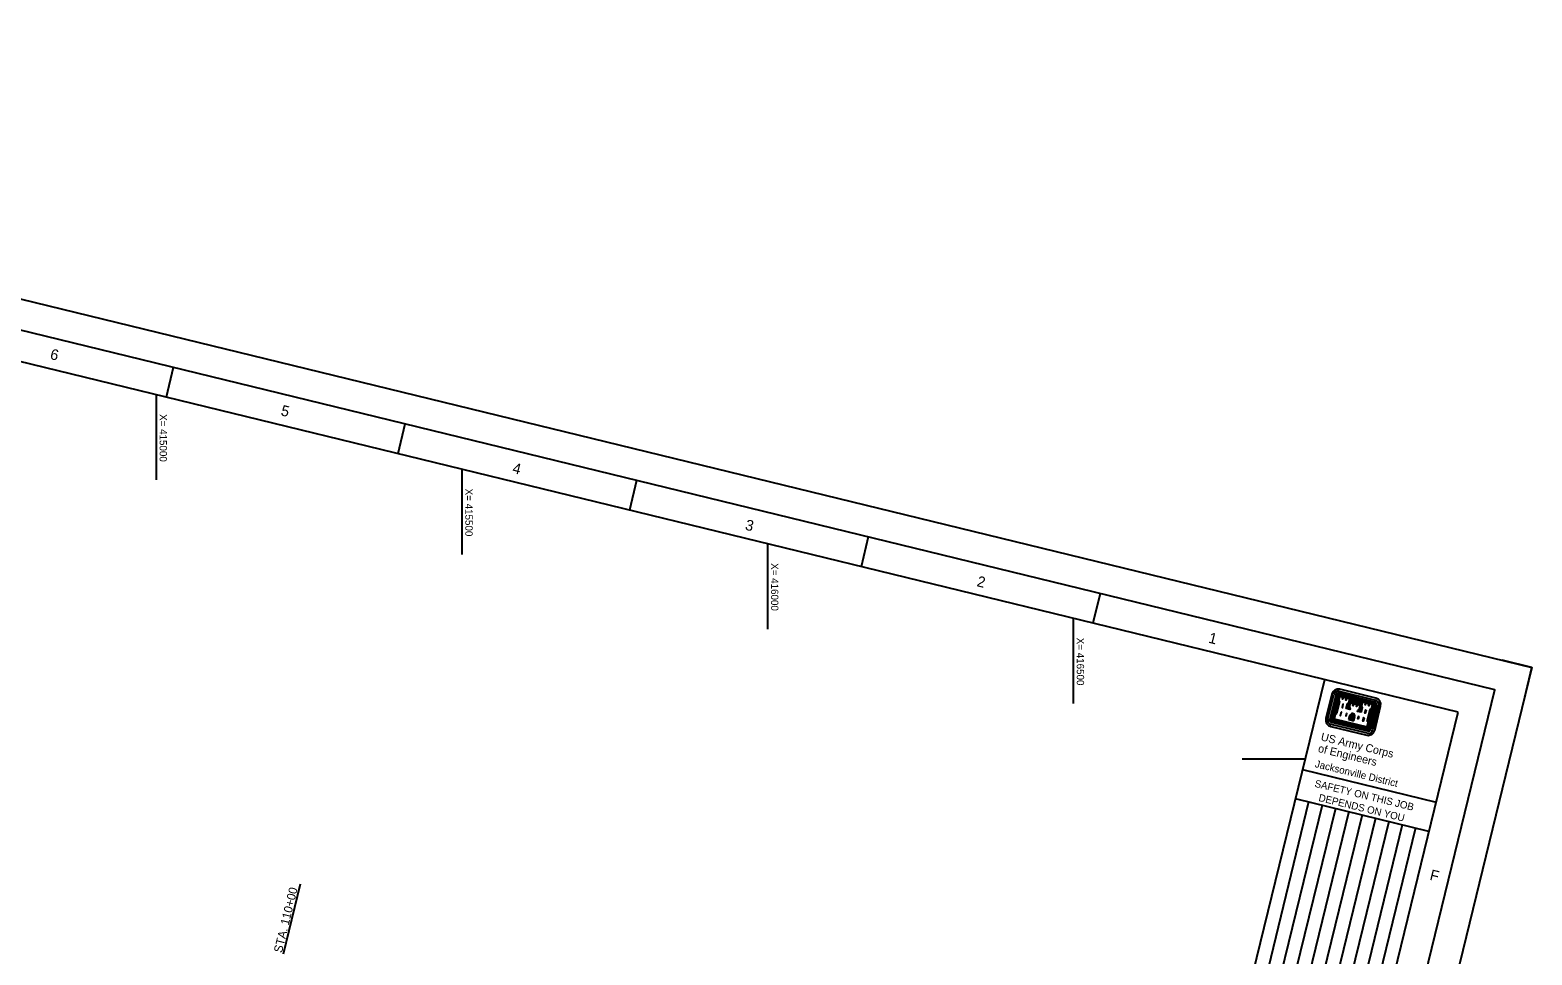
# Model space of a CAD drawing. Extents: x 412170 to 417250, y 1187847 to 1192192.
# Drawn here: x 414793 to 417250, y 1190679 to 1192192 of the extents above; entities that cross this region are included whole.
import ezdxf

# ---------------------------------------------------------------- set-up
doc = ezdxf.new("R2010")
doc.units = 0
for name, color, linetype in [('G-ANNO-NPLT', 7, 'Continuous'), ('G-ANNO-TEXT-LOGO', 7, 'Continuous'), ('G-ANNO-TEXT-TTLB', 7, 'Continuous'), ('G-ANNO-TTLB', 7, 'Continuous'), ('V-ALGN-TEXT', 7, 'Continuous'), ('V-TOPO-COOR-STAT', 7, 'Continuous')]:
    doc.layers.add(name, color=color, linetype=linetype)

msp = doc.modelspace()

# ---------------------------------------------------------------- linework, layer by layer
at = {"layer": 'G-ANNO-NPLT'}
msp.add_lwpolyline([(412975.1, 1192192.3), (417249.8, 1191149.8), (416444.2, 1187846.7), (412169.5, 1188889.2)], close=True, dxfattribs=at)
msp.add_lwpolyline([(417237.9, 1191101.3), (417249.8, 1191149.8), (417201.2, 1191161.7)], dxfattribs=at)
at = {"layer": 'G-ANNO-TEXT-LOGO'}
for p, q in [((416922.4, 1191106.1), (416912.7, 1191066.2)), ((416915.8, 1191065.5), (416925.5, 1191105.3)), ((416928.9, 1191104.5), (416919.2, 1191064.6)), ((416929.8, 1191104.3), (416920.1, 1191064.4)), ((416930.6, 1191104.1), (416920.9, 1191064.2)), ((416931.5, 1191103.9), (416921.7, 1191064)), ((416932.3, 1191103.6), (416922.6, 1191063.8)), ((416933.2, 1191103.4), (416923.6, 1191063.9)), ((416934, 1191103.2), (416924.6, 1191064.6)), ((416932.6, 1191094.6), (416927.6, 1191074.2)), ((416933.3, 1191093.5), (416928.7, 1191075)), ((416992, 1191089.7), (416933, 1191104.1)), ((416992.2, 1191090.6), (416933.2, 1191105)), ((416992.4, 1191091.3), (416933.4, 1191105.8)), ((416992.7, 1191092.2), (416933.6, 1191106.6)), ((416992.9, 1191093.1), (416933.8, 1191107.5)), ((416934.6, 1191110.8), (416993.7, 1191096.4)), ((416994.4, 1191099.5), (416935.4, 1191113.9)), ((416952, 1191093.3), (416970.1, 1191088.9)), ((416952.3, 1191094.1), (416970.3, 1191089.7)), ((416952.4, 1191094.9), (416970.5, 1191090.5)), ((416952.7, 1191095.8), (416970.7, 1191091.4)), ((416952.9, 1191096.7), (416970.9, 1191092.3)), ((416953.1, 1191097.5), (416971.1, 1191093)), ((416953.3, 1191098.3), (416971.3, 1191093.9)), ((416950.4, 1191064.3), (416952, 1191070.8)), ((416951.2, 1191064.1), (416952.8, 1191070.6)), ((416952.1, 1191063.9), (416953.7, 1191070.4)), ((416953, 1191063.7), (416954.6, 1191070.2)), ((416953.7, 1191063.5), (416955.3, 1191070)), ((416954.9, 1191063.2), (416956.5, 1191069.7)), ((416955.7, 1191063.1), (416957.3, 1191069.6)), ((416956.6, 1191062.8), (416958.1, 1191069.3)), ((416957.4, 1191062.6), (416959, 1191069.1)), ((416958.2, 1191062.4), (416959.8, 1191068.9)), ((416990.7, 1191089.4), (416981.3, 1191050.7)), ((416991.5, 1191089.2), (416981.9, 1191049.7)), ((416986.9, 1191080.5), (416982.4, 1191061.9)), ((416992.4, 1191089), (416982.7, 1191049.2)), ((416988, 1191081), (416983, 1191060.8)), ((416993.3, 1191088.8), (416983.5, 1191049)), ((416994, 1191088.6), (416984.3, 1191048.8)), ((416994.9, 1191088.4), (416985.2, 1191048.5)), ((416995.8, 1191088.2), (416986.1, 1191048.3)), ((416999.1, 1191087.4), (416989.4, 1191047.5)), ((416992.6, 1191046.7), (417002.3, 1191086.6)), ((416920.6, 1191053.2), (416979.6, 1191038.8)), ((416980.4, 1191042), (416921.3, 1191056.4)), ((416981.2, 1191045.4), (416922.2, 1191059.8)), ((416981.4, 1191046.2), (416922.4, 1191060.6)), ((416981.6, 1191047), (416922.6, 1191061.5)), ((416981.8, 1191047.9), (416922.8, 1191062.3)), ((416982, 1191048.7), (416923, 1191063.1)), ((416981.9, 1191049.7), (416923.6, 1191063.9)), ((416981.3, 1191050.7), (416924.6, 1191064.6)), ((416950.4, 1191064.3), (416958.2, 1191062.4))]:
    msp.add_line(p, q, dxfattribs=at)
for points in [[(416934.7, 1191103.1), (416932.8, 1191095.4), (416934, 1191093.3), (416929.5, 1191074.8), (416927.4, 1191073.4), (416925.4, 1191065), (416980.8, 1191051.5), (416982.8, 1191059.9), (416981.5, 1191062.1), (416986, 1191080.7), (416988.2, 1191081.9), (416990, 1191089.6), (416982.8, 1191091.3), (416977.1, 1191092.7), (416971.9, 1191094), (416970, 1191086.3), (416971.5, 1191084.2), (416969.8, 1191077.4), (416965.7, 1191078.4), (416965.9, 1191079.1), (416968.1, 1191080.4), (416969.9, 1191088), (416962.6, 1191089.8), (416957, 1191091.1), (416951.8, 1191092.4), (416950, 1191084.8), (416951.3, 1191082.6), (416951.1, 1191082), (416947.1, 1191083), (416948.7, 1191089.8), (416950.9, 1191091), (416952.7, 1191098.7), (416945.5, 1191100.4), (416939.8, 1191101.8), (416934.7, 1191103.1)], [(416935.2, 1191102), (416933.7, 1191095.6), (416935, 1191093.4), (416930.3, 1191074.2), (416928.1, 1191072.9), (416926.4, 1191065.7), (416980.2, 1191052.5), (416981.9, 1191059.7), (416980.5, 1191061.9), (416985.2, 1191081.2), (416987.5, 1191082.5), (416989.1, 1191088.9), (416983.8, 1191090.2), (416983.1, 1191087.1), (416982.6, 1191087.3), (416983.3, 1191090.3), (416978.2, 1191091.5), (416977.4, 1191088.5), (416977.1, 1191088.6), (416977.8, 1191091.6), (416972.5, 1191092.9), (416971, 1191086.5), (416972.3, 1191084.3), (416970.4, 1191076.5), (416964.7, 1191077.8), (416965.2, 1191079.7), (416967.4, 1191081), (416968.9, 1191087.4), (416963.7, 1191088.7), (416963, 1191085.7), (416962.6, 1191085.8), (416963.3, 1191088.8), (416958.1, 1191090.1), (416957.3, 1191087), (416956.8, 1191087.2), (416957.6, 1191090.2), (416952.4, 1191091.4), (416950.9, 1191085), (416952.2, 1191082.8), (416951.7, 1191081), (416946.1, 1191082.4), (416948, 1191090.2), (416950.2, 1191091.6), (416951.7, 1191098), (416946.6, 1191099.2), (416945.9, 1191096.2), (416945.4, 1191096.3), (416946.1, 1191099.4), (416940.9, 1191100.6), (416940.1, 1191097.6), (416939.7, 1191097.7), (416940.5, 1191100.7), (416935.2, 1191102)], [(416937.5, 1191076.7), (416936.1, 1191071), (416936.7, 1191070.9), (416938.1, 1191076.6), (416937.5, 1191076.7)], [(416940.7, 1191089.7), (416939.3, 1191084), (416939.9, 1191083.9), (416941.2, 1191089.5), (416940.7, 1191089.7)], [(416946.5, 1191074.6), (416945.5, 1191070.6), (416946, 1191070.5), (416946.9, 1191074.4), (416946.5, 1191074.6)], [(416950.1, 1191089.5), (416949.5, 1191089.2), (416948.1, 1191083.6), (416950, 1191083.2), (416949, 1191084.7), (416950.2, 1191089.6)], [(416966.5, 1191069.7), (416965.5, 1191065.7), (416965, 1191065.8), (416966, 1191069.8), (416966.5, 1191069.7)], [(416970.1, 1191084.6), (416970.5, 1191084), (416969.1, 1191078.5), (416967.4, 1191078.9), (416968.9, 1191079.9), (416970, 1191084.8)], [(416975.3, 1191067.5), (416973.9, 1191061.8), (416973.4, 1191061.9), (416974.8, 1191067.6), (416975.3, 1191067.5)], [(416978.5, 1191080.5), (416977.1, 1191074.8), (416976.6, 1191074.9), (416978, 1191080.6), (416978.5, 1191080.5)]]:
    msp.add_lwpolyline(points, dxfattribs=at)
for centre, major_axis, start_param, end_param in [((416932.9, 1191103.5), (10.4, -2.5), 1.57078, 3.141576), ((416932.9, 1191103.5), (7.28, -1.77), 1.57078, 3.141576), ((416932.9, 1191103.5), (3.9, -0.95), 1.57078, 3.141576), ((416932.9, 1191103.5), (3.06, -0.75), 1.57078, 3.141576), ((416932.9, 1191103.5), (2.22, -0.54), 1.57078, 3.141576), ((416932.9, 1191103.5), (1.37, -0.33), 1.57078, 3.141576), ((416932.9, 1191103.5), (0.53, -0.129), 1.57078, 3.141576), ((416991.8, 1191089.1), (2.22, -0.54), 6.283169, 7.853965), ((416991.8, 1191089.1), (3.06, -0.75), 6.283169, 7.853965), ((416991.8, 1191089.1), (3.9, -0.95), 6.283169, 7.853965), ((416991.8, 1191089.1), (7.28, -1.77), 6.28317, 7.853966), ((416991.8, 1191089.1), (10.4, -2.5), 6.283169, 7.853965), ((416923.1, 1191063.6), (-10.4, 2.5), 6.28317, 7.853966), ((416957.2, 1191069.1), (-5.4, 1.32), 4.985832, 6.214359), ((416957.2, 1191069.1), (-4.55, 1.11), 4.947465, 6.21436), ((416957.2, 1191069.1), (-3.71, 0.9), 4.947465, 6.21436), ((416957.2, 1191069.1), (-2.87, 0.7), 4.947465, 6.21436), ((416954.3, 1191069.8), (2.02, -0.49), 0.068794, 1.335689), ((416957.2, 1191069.1), (-2.02, 0.49), 4.947465, 6.214359), ((416954.3, 1191069.8), (2.87, -0.7), 0.068794, 1.335689), ((416954.3, 1191069.8), (3.71, -0.9), 0.068795, 1.335689), ((416954.3, 1191069.8), (4.55, -1.11), 0.068795, 1.335689), ((416954.3, 1191069.8), (5.4, -1.32), 0.068795, 1.29842), ((416991.8, 1191089.1), (0.53, -0.129), 6.283169, 7.853965), ((416991.8, 1191089.1), (1.37, -0.33), 6.283169, 7.853965), ((416923.1, 1191063.6), (-7.28, 1.77), 6.28317, 7.853966), ((416923.1, 1191063.6), (-3.9, 0.95), 6.28317, 7.853966), ((416923.1, 1191063.6), (-3.06, 0.75), 6.28317, 7.853966), ((416923.1, 1191063.6), (-2.22, 0.54), 6.28317, 7.853966), ((416923.1, 1191063.6), (-1.37, 0.33), 6.28317, 7.853966), ((416923.1, 1191063.6), (-0.53, 0.129), 6.28317, 7.853966), ((416982.1, 1191049.3), (10.4, -2.5), 4.712373, 6.28317), ((416982.1, 1191049.3), (-7.28, 1.77), 1.570781, 3.141577), ((416982.1, 1191049.3), (3.9, -0.95), 4.712373, 6.28317), ((416982.1, 1191049.3), (3.06, -0.75), 4.712373, 6.28317), ((416982.1, 1191049.3), (2.22, -0.54), 4.712373, 6.28317), ((416982.1, 1191049.3), (1.37, -0.33), 4.712373, 6.28317), ((416982.1, 1191049.3), (0.53, -0.129), 4.712373, 6.28317)]:
    msp.add_ellipse(centre, major_axis=major_axis, ratio=0.99964, start_param=start_param, end_param=end_param, dxfattribs=at)
at = {"layer": 'G-ANNO-TTLB'}
for p, q in [((415027.7, 1191640.3), (415015.9, 1191591.7)), ((415406.6, 1191547.9), (415394.8, 1191499.3)), ((415785.5, 1191455.5), (415773.6, 1191406.9)), ((416164.4, 1191363.1), (416152.5, 1191314.5)), ((416543.3, 1191270.7), (416531.4, 1191222.1)), ((416910.3, 1191129.7), (416152.1, 1188020.8)), ((416874.5, 1190982.8), (417093.1, 1190929.4)), ((416884.5, 1190929.7), (416686, 1190115.7)), ((416906.4, 1190924.4), (416707.9, 1190110.4)), ((416928.2, 1190919.1), (416729.7, 1190105)), ((416862.3, 1190935.2), (417080.8, 1190881.9)), ((416950.1, 1190913.8), (416751.6, 1190099.7)), ((416972, 1190908.4), (416773.4, 1190094.4)), ((416993.8, 1190903.1), (416795.3, 1190089)), ((417015.7, 1190897.8), (416817.2, 1190083.7)), ((417037.5, 1190892.4), (416839, 1190078.4)), ((417059.4, 1190887.1), (416860.9, 1190073))]:
    msp.add_line(p, q, dxfattribs=at)
for points in [[(412229.9, 1188925.9), (416407.5, 1187907.1), (417189.3, 1191113.1), (413011.8, 1192131.9)], [(417128.9, 1191076.4), (413121.4, 1192053.7), (412363.2, 1188944.8), (416370.7, 1187967.5)]]:
    msp.add_lwpolyline(points, close=True, dxfattribs=at)
at = {"layer": 'V-ALGN-TEXT'}
msp.add_line((415208, 1190681.2), (415235.9, 1190796), dxfattribs=at)
at = {"layer": 'V-TOPO-COOR-STAT'}
for p, q in [((415000, 1191456.4), (415000, 1191595.3)), ((415500, 1191334.4), (415500, 1191473.4)), ((416000, 1191212.5), (416000, 1191351.4)), ((416500, 1191090.5), (416500, 1191229.5)), ((416775.7, 1191000), (416878.7, 1191000))]:
    msp.add_line(p, q, dxfattribs=at)

# ---------------------------------------------------------------- texts
at = {"layer": 'G-ANNO-TEXT-TTLB'}
for s, height, p in [('US Army Corps', 13.086, (416903.6, 1191030.5)), ('of Engineers', 13.086, (416899, 1191011.6)), ('Jacksonville District', 11.9, (416894, 1190986.8)), ('SAFETY ON THIS JOB', 11.9, (416893.5, 1190954.6)), ('DEPENDS ON YOU', 11.9, (416899.9, 1190931.5))]:
    msp.add_text(s, height=height, rotation=346.2946, dxfattribs=at).set_placement(p)
at = {"layer": 'G-ANNO-TTLB'}
for s, p in [('6', (414825.1, 1191654.4)), ('5', (415202.5, 1191562.3)), ('4', (415581.3, 1191468)), ('3', (415961.9, 1191375.2)), ('2', (416340.8, 1191282.8)), ('1', (416719.7, 1191190.4)), ('F', (417081.5, 1190802.5))]:
    msp.add_text(s, height=17.5, rotation=346.2946, dxfattribs=at).set_placement(p)
at = {"layer": 'V-ALGN-TEXT'}
msp.add_text('STA. 110+00', height=13.92, rotation=76.2946, dxfattribs=at).set_placement((415205.3, 1190682))
at = {"layer": 'V-TOPO-COOR-STAT'}
for s, p in [('X= 415000', (415005.3, 1191564.1)), ('X= 415500', (415505.3, 1191442.2)), ('X= 416000', (416005.3, 1191320.3)), ('X= 416500', (416505.3, 1191198.3))]:
    msp.add_text(s, height=12, rotation=270, dxfattribs=at).set_placement(p)

doc.saveas('drawing.dxf')
